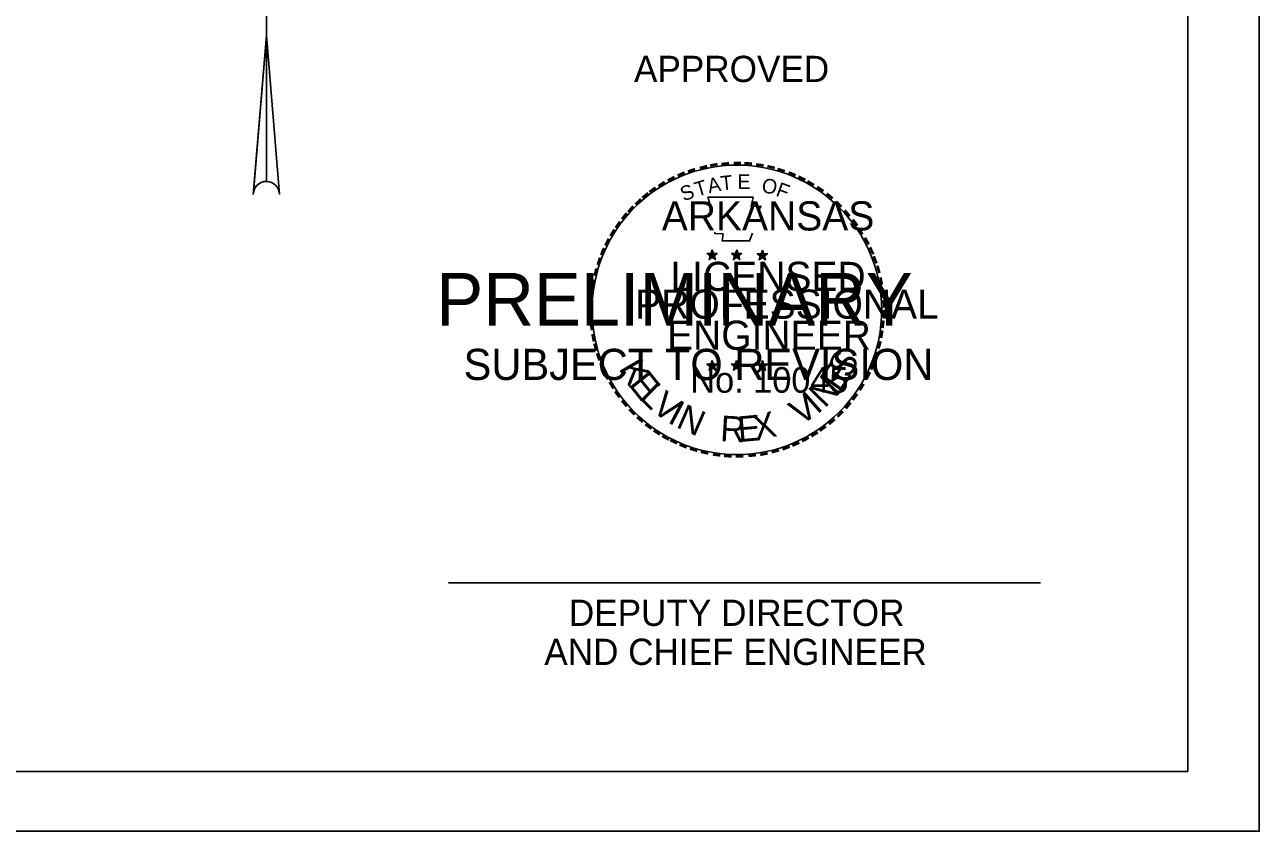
# Model space of a CAD drawing. Extents: x 1382482 to 1385815, y 1168351 to 1170484.
# Drawn here: x 1384993 to 1385815, y 1168351 to 1168888 of the extents above; entities that cross this region are included whole.
import ezdxf

# ---------------------------------------------------------------- set-up
doc = ezdxf.new("R2010")
doc.units = 0
for name, color, linetype in [('R_Border', 7, 'Continuous'), ('R_Border PE', 7, 'Continuous'), ('R_Border Prem', 7, 'Continuous'), ('R_Draft', 7, 'Continuous'), ('R_No Plot', 7, 'Continuous')]:
    doc.layers.add(name, color=color, linetype=linetype)

msp = doc.modelspace()

# ---------------------------------------------------------------- linework, layer by layer
at = {"layer": 'R_Border'}
for q in [(1385767.76, 1170445.2), (1382605.96, 1168390.6)]:
    msp.add_line((1385767.76, 1168390.6), q, dxfattribs=at)
at = {"layer": 'R_Border PE'}
for p, q in [((1385447.42, 1168735.73), (1385450.82, 1168734.63)), ((1385447.42, 1168735.73), (1385449.92, 1168735.33)), ((1385447.42, 1168735.73), (1385449.72, 1168734.53)), ((1385448.72, 1168731.73), (1385450.82, 1168734.63)), ((1385448.72, 1168731.73), (1385449.92, 1168734.13)), ((1385448.72, 1168731.73), (1385450.72, 1168733.83)), ((1385450.82, 1168738.23), (1385450.42, 1168735.73)), ((1385452.92, 1168731.73), (1385450.72, 1168733.83)), ((1385450.82, 1168734.63), (1385450.82, 1168738.23)), ((1385450.82, 1168738.23), (1385451.32, 1168735.83)), ((1385454.12, 1168735.73), (1385450.82, 1168734.63)), ((1385452.92, 1168731.73), (1385450.82, 1168734.63)), ((1385454.12, 1168735.73), (1385451.42, 1168735.23)), ((1385452.92, 1168731.73), (1385451.52, 1168734.53)), ((1385454.12, 1168735.73), (1385452.22, 1168734.73)), ((1385463.72, 1168735.73), (1385467.12, 1168734.63)), ((1385463.72, 1168735.73), (1385466.12, 1168735.33)), ((1385463.72, 1168735.73), (1385465.92, 1168734.53)), ((1385464.92, 1168731.73), (1385467.12, 1168734.63)), ((1385464.92, 1168731.73), (1385466.22, 1168734.13)), ((1385464.92, 1168731.73), (1385467.02, 1168733.83)), ((1385467.12, 1168738.23), (1385466.72, 1168735.73)), ((1385469.12, 1168731.73), (1385467.02, 1168733.83)), ((1385467.12, 1168734.63), (1385467.12, 1168738.23)), ((1385467.12, 1168738.23), (1385467.52, 1168735.83)), ((1385470.42, 1168735.73), (1385467.12, 1168734.63)), ((1385469.12, 1168731.73), (1385467.12, 1168734.63)), ((1385470.42, 1168735.73), (1385467.62, 1168735.23)), ((1385469.12, 1168731.73), (1385467.72, 1168734.53)), ((1385470.42, 1168735.73), (1385468.42, 1168734.73)), ((1385480.82, 1168735.63), (1385484.22, 1168734.53)), ((1385480.82, 1168735.63), (1385483.22, 1168735.13)), ((1385480.82, 1168735.63), (1385483.12, 1168734.43)), ((1385482.02, 1168731.63), (1385484.22, 1168734.53)), ((1385482.02, 1168731.63), (1385483.32, 1168734.03)), ((1385482.02, 1168731.63), (1385484.22, 1168733.73)), ((1385484.22, 1168738.03), (1385483.82, 1168735.63)), ((1385484.22, 1168734.53), (1385484.22, 1168738.03)), ((1385484.22, 1168738.03), (1385484.62, 1168735.63)), ((1385487.62, 1168735.63), (1385484.22, 1168734.53)), ((1385486.22, 1168731.63), (1385484.22, 1168734.53)), ((1385486.22, 1168731.63), (1385484.22, 1168733.73)), ((1385487.62, 1168735.63), (1385484.72, 1168735.13)), ((1385486.22, 1168731.63), (1385484.92, 1168734.43)), ((1385487.62, 1168735.63), (1385485.52, 1168734.63)), ((1385447.32, 1168662.13), (1385450.72, 1168661.03)), ((1385447.32, 1168662.13), (1385449.92, 1168661.63)), ((1385447.32, 1168662.13), (1385449.72, 1168660.93)), ((1385448.72, 1168658.13), (1385450.72, 1168661.03)), ((1385448.72, 1168658.13), (1385449.92, 1168660.53)), ((1385448.72, 1168658.13), (1385450.72, 1168660.33)), ((1385450.72, 1168664.53), (1385450.32, 1168662.13)), ((1385450.72, 1168661.03), (1385450.72, 1168664.53)), ((1385450.72, 1168664.53), (1385451.22, 1168662.13)), ((1385454.12, 1168662.13), (1385450.72, 1168661.03)), ((1385452.92, 1168658.13), (1385450.72, 1168661.03)), ((1385452.92, 1168658.13), (1385450.72, 1168660.23)), ((1385454.12, 1168662.13), (1385451.32, 1168661.63)), ((1385452.92, 1168658.13), (1385451.52, 1168660.93)), ((1385454.12, 1168662.13), (1385452.22, 1168661.13)), ((1385463.62, 1168662.13), (1385467.02, 1168661.03)), ((1385463.62, 1168662.13), (1385466.12, 1168661.63)), ((1385463.62, 1168662.13), (1385465.92, 1168660.93)), ((1385464.92, 1168658.13), (1385467.02, 1168661.03)), ((1385464.92, 1168658.13), (1385466.12, 1168660.53)), ((1385464.92, 1168658.13), (1385467.02, 1168660.33)), ((1385467.02, 1168664.53), (1385466.62, 1168662.13)), ((1385467.02, 1168661.03), (1385467.02, 1168664.53)), ((1385467.02, 1168664.53), (1385467.42, 1168662.13)), ((1385470.42, 1168662.13), (1385467.02, 1168661.03)), ((1385469.02, 1168658.13), (1385467.02, 1168661.03)), ((1385469.02, 1168658.13), (1385467.02, 1168660.23)), ((1385470.42, 1168662.13), (1385467.52, 1168661.63)), ((1385469.02, 1168658.13), (1385467.72, 1168660.93)), ((1385470.42, 1168662.13), (1385468.32, 1168661.13)), ((1385480.82, 1168662.03), (1385484.22, 1168660.93)), ((1385480.82, 1168662.03), (1385483.22, 1168661.53)), ((1385480.82, 1168662.03), (1385483.12, 1168660.83)), ((1385482.02, 1168658.03), (1385484.22, 1168660.93)), ((1385482.02, 1168658.03), (1385483.32, 1168660.43)), ((1385482.02, 1168658.03), (1385484.22, 1168660.23)), ((1385484.22, 1168664.43), (1385483.82, 1168662.03)), ((1385484.22, 1168660.93), (1385484.22, 1168664.43)), ((1385484.22, 1168664.43), (1385484.62, 1168662.03)), ((1385487.62, 1168662.03), (1385484.22, 1168660.93)), ((1385486.22, 1168658.03), (1385484.22, 1168660.93)), ((1385486.22, 1168658.03), (1385484.22, 1168660.13)), ((1385487.62, 1168662.03), (1385484.72, 1168661.53)), ((1385486.22, 1168658.03), (1385484.82, 1168660.83)), ((1385487.62, 1168662.03), (1385485.52, 1168661.03)), ((1385275.11, 1168516.37), (1385669.46, 1168516.37))]:
    msp.add_line(p, q, dxfattribs=at)
for points in [[(1385447.82, 1168773.43), (1385450.42, 1168765.33)], [(1385481.92, 1168764.53), (1385483.32, 1168767.23), (1385476.72, 1168767.03), (1385478.02, 1168773.43), (1385447.82, 1168773.43)], [(1385452.62, 1168749.93), (1385452.62, 1168749.03), (1385458.02, 1168748.83), (1385457.52, 1168744.23), (1385475.72, 1168744.23), (1385477.72, 1168749.43)], [(1385450.82, 1168738.23), (1385452.92, 1168731.73), (1385447.42, 1168735.73), (1385454.12, 1168735.73), (1385448.72, 1168731.73), (1385450.82, 1168738.23)], [(1385467.12, 1168738.23), (1385469.12, 1168731.73), (1385463.72, 1168735.73), (1385470.42, 1168735.73), (1385464.92, 1168731.73), (1385467.12, 1168738.23)], [(1385484.22, 1168738.03), (1385486.22, 1168731.63), (1385480.82, 1168735.63), (1385487.62, 1168735.63), (1385482.02, 1168731.63), (1385484.22, 1168738.03)], [(1385450.72, 1168664.53), (1385452.92, 1168658.13), (1385447.32, 1168662.13), (1385454.12, 1168662.13), (1385448.72, 1168658.13), (1385450.72, 1168664.53)], [(1385467.02, 1168664.53), (1385469.02, 1168658.13), (1385463.62, 1168662.13), (1385470.42, 1168662.13), (1385464.92, 1168658.13), (1385467.02, 1168664.53)], [(1385484.22, 1168664.43), (1385486.22, 1168658.03), (1385480.82, 1168662.03), (1385487.62, 1168662.03), (1385482.02, 1168658.03), (1385484.22, 1168664.43)]]:
    msp.add_lwpolyline(points, dxfattribs=at)
for centre, radius in [((1385467.26, 1168698.24), 96.45), ((1385450.73, 1168734.61), 1.67), ((1385450.73, 1168734.61), 1.41), ((1385450.73, 1168734.61), 1.13), ((1385450.73, 1168734.61), 0.963), ((1385450.73, 1168734.61), 0.726), ((1385450.73, 1168734.61), 0.482), ((1385450.73, 1168734.61), 0.288), ((1385466.96, 1168734.61), 1.67), ((1385466.96, 1168734.61), 1.41), ((1385466.96, 1168734.61), 1.13), ((1385466.96, 1168734.61), 0.963), ((1385466.96, 1168734.61), 0.726), ((1385466.96, 1168734.61), 0.482), ((1385466.96, 1168734.61), 0.288), ((1385484.11, 1168734.5), 1.67), ((1385484.11, 1168734.5), 1.41), ((1385484.11, 1168734.5), 1.13), ((1385484.11, 1168734.5), 0.963), ((1385484.11, 1168734.5), 0.726), ((1385484.11, 1168734.5), 0.482), ((1385484.11, 1168734.5), 0.288), ((1385450.69, 1168661.01), 1.67), ((1385450.69, 1168661.01), 1.41), ((1385450.69, 1168661.01), 1.13), ((1385450.69, 1168661.01), 0.963), ((1385450.69, 1168661.01), 0.726), ((1385450.69, 1168661.01), 0.482), ((1385450.69, 1168661.01), 0.288), ((1385466.92, 1168661.01), 1.67), ((1385466.92, 1168661.01), 1.41), ((1385466.92, 1168661.01), 1.13), ((1385466.92, 1168661.01), 0.963), ((1385466.92, 1168661.01), 0.726), ((1385466.92, 1168661.01), 0.482), ((1385466.92, 1168661.01), 0.288), ((1385484.09, 1168660.91), 1.67), ((1385484.09, 1168660.91), 1.41), ((1385484.09, 1168660.91), 1.13), ((1385484.09, 1168660.91), 0.963), ((1385484.09, 1168660.91), 0.726), ((1385484.09, 1168660.91), 0.482), ((1385484.09, 1168660.91), 0.288)]:
    msp.add_circle(centre, radius, dxfattribs=at)
at = {"layer": 'R_Draft'}
for p, q in [((1385153.81, 1168921.83), (1385153.81, 1168809.78)), ((1385153.81, 1168880.95), (1385145.18, 1168776.51)), ((1385153.81, 1168783.82), (1385153.81, 1168880.95))]:
    msp.add_line(p, q, dxfattribs=at)
msp.add_lwpolyline([(1385162.56, 1168775.07), (1385153.81, 1168880.95), (1385145.06, 1168775.07)], dxfattribs=at)
for start, end in [(0, 180), (90, 170.5511)]:
    msp.add_arc((1385153.81, 1168775.07), 8.75, start, end, dxfattribs=at)
at = {"layer": 'R_No Plot'}
msp.add_line((1382481.95, 1168350.81), (1385815.28, 1168350.81), dxfattribs=at)
msp.add_lwpolyline([(1382481.88, 1170484.15), (1385815.28, 1170484.15), (1385815.28, 1168350.77), (1382481.88, 1168350.77)], close=True, dxfattribs=at)

# ---------------------------------------------------------------- texts
at = {"layer": 'R_Border PE'}
for s, height, p in [('APPROVED', 17.496, (1385398.72, 1168850.03)), ('ARKANSAS', 19.44, (1385417.22, 1168751.13)), ('LICENSED', 19.44, (1385423.02, 1168710.83)), ('PROFESSIONAL', 19.44, (1385399.52, 1168692.33)), ('ENGINEER', 19.44, (1385420.72, 1168671.63)), ('No. 10045', 17.078, (1385436.22, 1168643.03)), ('DEPUTY DIRECTOR', 17.496, (1385355.34, 1168487.64)), ('AND CHIEF ENGINEER', 17.496, (1385338.95, 1168461.64))]:
    msp.add_text(s, height=height, dxfattribs=at).set_placement(p)
for s, height, rotation, p in [('-', 15.55, 5.89682, (1385456.62, 1168789.33)), ('-', 15.55, 0.18623, (1385464.12, 1168790.03)), ('-', 15.55, 357.74304, (1385471.12, 1168789.93)), ('-', 15.55, 24.30721, (1385429.42, 1168781.83)), ('-', 15.55, 19.17608, (1385435.72, 1168784.43)), ('-', 15.55, 13.63015, (1385443.02, 1168786.73)), ('-', 15.55, 10.21935, (1385449.52, 1168788.33)), ('E', 9.72, 0.83234, (1385467.72, 1168778.73)), ('-', 15.55, 352.16173, (1385478.32, 1168789.33)), ('-', 15.55, 347.20489, (1385485.32, 1168788.33)), ('-', 15.55, 342.3362, (1385491.62, 1168786.73)), ('-', 15.55, 337.85509, (1385498.62, 1168784.63)), ('-', 15.55, 36.23174, (1385411.82, 1168771.33)), ('-', 15.55, 34.06357, (1385417.52, 1168775.13)), ('-', 15.55, 28.79182, (1385423.32, 1168778.73)), ('S', 9.72, 21.59401, (1385431.82, 1168770.33)), ('T', 9.72, 16.4036, (1385440.72, 1168773.53)), ('A', 9.72, 11.21318, (1385448.72, 1168775.93)), ('T', 9.72, 6.02276, (1385456.92, 1168777.63)), ('O', 9.72, 350.4515, (1385483.32, 1168776.63)), ('F', 9.72, 340.07066, (1385492.62, 1168774.43)), ('-', 15.55, 334.12109, (1385504.82, 1168782.03)), ('-', 15.55, 329.64089, (1385510.42, 1168779.23)), ('-', 15.55, 325.86266, (1385516.62, 1168775.73)), ('-', 15.55, 42.96224, (1385403.12, 1168763.53)), ('-', 15.55, 38.95066, (1385407.32, 1168767.63)), ('-', 15.55, 320.52971, (1385522.62, 1168771.63)), ('-', 15.55, 48.42305, (1385398.72, 1168758.83)), ('-', 15.55, 315.57859, (1385528.42, 1168766.83)), ('-', 15.55, 309.87973, (1385533.92, 1168761.43)), ('-', 15.55, 54.23247, (1385390.82, 1168748.63)), ('-', 15.55, 50.61417, (1385394.72, 1168754.23)), ('-', 15.55, 306.65218, (1385539.12, 1168755.63)), ('-', 15.55, 58.07063, (1385387.62, 1168743.53)), ('-', 13.61, 303.67529, (1385543.72, 1168750.13)), ('-', 15.55, 67.77427, (1385382.02, 1168731.63)), ('-', 15.55, 62.87135, (1385384.52, 1168737.53)), ('-', 15.55, 299.66835, (1385546.92, 1168744.13)), ('-', 15.55, 294.66279, (1385550.12, 1168738.23)), ('-', 15.55, 72.39447, (1385380.02, 1168725.53)), ('-', 15.55, 290.57283, (1385552.52, 1168732.73)), ('-', 15.55, 75.46096, (1385378.02, 1168718.53)), ('-', 15.55, 285.12326, (1385554.82, 1168727.03)), ('-', 15.55, 81.20126, (1385376.82, 1168711.63)), ('-', 15.55, 280.54934, (1385556.82, 1168719.73)), ('-', 15.55, 85.18634, (1385376.02, 1168704.93)), ('-', 15.55, 276.59616, (1385558.32, 1168712.43)), ('-', 15.55, 89.06224, (1385375.82, 1168698.13)), ('-', 15.55, 274.33011, (1385558.92, 1168705.33)), ('-', 15.55, 269.94067, (1385559.22, 1168699.13)), ('-', 15.55, 94.19588, (1385376.12, 1168691.03)), ('-', 15.55, 263.5172, (1385559.02, 1168692.73)), ('-', 15.55, 98.94793, (1385376.82, 1168684.63)), ('-', 15.55, 101.71495, (1385378.12, 1168677.43)), ('-', 15.55, 260.99529, (1385558.32, 1168686.33)), ('-', 15.55, 105.45785, (1385379.72, 1168671.63)), ('-', 15.55, 255.7626, (1385557.32, 1168679.73)), ('-', 15.55, 109.08742, (1385381.72, 1168665.53)), ('K', 17.08, 300.31651, (1385388.18, 1168659.32)), ('S', 17.08, 62.31272, (1385542.16, 1168651.8)), ('-', 15.55, 252.86809, (1385555.52, 1168672.73)), ('-', 15.55, 114.06432, (1385384.22, 1168659.73)), ('-', 15.55, 115.72885, (1385387.22, 1168653.73)), ('E', 17.08, 308.55476, (1385394.57, 1168648.39)), ('E', 17.08, 54.95088, (1385535.6, 1168642.58)), ('-', 15.55, 244.61971, (1385550.82, 1168660.13)), ('-', 15.55, 247.88866, (1385553.42, 1168666.23)), ('-', 15.55, 120.44712, (1385390.72, 1168648.03)), ('L', 17.08, 315.9166, (1385401.56, 1168639.49)), ('N', 17.08, 45.66094, (1385525.71, 1168632.28)), ('-', 15.55, 239.07125, (1385547.02, 1168652.83)), ('-', 15.55, 125.89344, (1385394.52, 1168642.63)), ('V', 17.08, 323.27844, (1385409.63, 1168631.55)), ('V', 17.08, 32.69008, (1385509.42, 1168620.84)), ('I', 17.08, 41.45417, (1385520.72, 1168628.17)), ('-', 15.55, 233.84524, (1385543.12, 1168646.53)), ('-', 15.55, 130.71812, (1385399.12, 1168637.13)), ('-', 15.55, 134.22381, (1385404.12, 1168631.93)), ('I', 17.08, 332.04253, (1385420.46, 1168623.55)), ('N', 17.08, 336.2493, (1385426.06, 1168620.32)), ('-', 15.55, 231.25377, (1385538.92, 1168640.93)), ('-', 15.55, 138.93382, (1385409.22, 1168627.43)), ('R', 17.08, 356.66964, (1385455.84, 1168610.85)), ('E', 17.08, 4.90789, (1385468.48, 1168610.11)), ('X', 17.08, 12.26973, (1385479.76, 1168610.99)), ('-', 15.55, 221.08509, (1385529.22, 1168630.53)), ('-', 15.55, 225.76533, (1385534.22, 1168635.53)), ('-', 15.55, 144.64634, (1385414.62, 1168623.43)), ('-', 15.55, 148.08978, (1385420.02, 1168619.83)), ('-', 15.55, 212.24909, (1385518.72, 1168622.23)), ('-', 15.55, 215.73633, (1385523.82, 1168626.03)), ('-', 15.55, 151.57039, (1385425.62, 1168616.63)), ('-', 15.55, 154.60019, (1385430.82, 1168614.33)), ('-', 15.55, 158.56121, (1385436.82, 1168611.83)), ('-', 15.55, 200.71842, (1385501.22, 1168613.03)), ('-', 15.55, 204.25161, (1385507.22, 1168615.63)), ('-', 15.55, 207.35684, (1385513.22, 1168618.83)), ('-', 15.55, 162.79826, (1385443.52, 1168609.73)), ('-', 15.55, 167.55551, (1385450.42, 1168608.23)), ('-', 15.55, 173.11546, (1385457.92, 1168607.13)), ('-', 15.55, 176.51827, (1385465.03, 1168606.55)), ('-', 15.55, 181.59176, (1385472.33, 1168606.75)), ('-', 15.55, 185.81666, (1385480.32, 1168607.53)), ('-', 15.55, 191.28576, (1385487.52, 1168608.73)), ('-', 15.55, 195.47429, (1385494.62, 1168610.73))]:
    msp.add_text(s, height=height, rotation=rotation, dxfattribs=at).set_placement(p)
at = {"layer": 'R_Border Prem'}
for s, height, p in [('PRELIMINARY', 35, (1385267.08, 1168687.81)), ('SUBJECT TO REVISION', 20.7511, (1385285.17, 1168651.52))]:
    msp.add_text(s, height=height, dxfattribs=at).set_placement(p)

doc.saveas('drawing.dxf')
